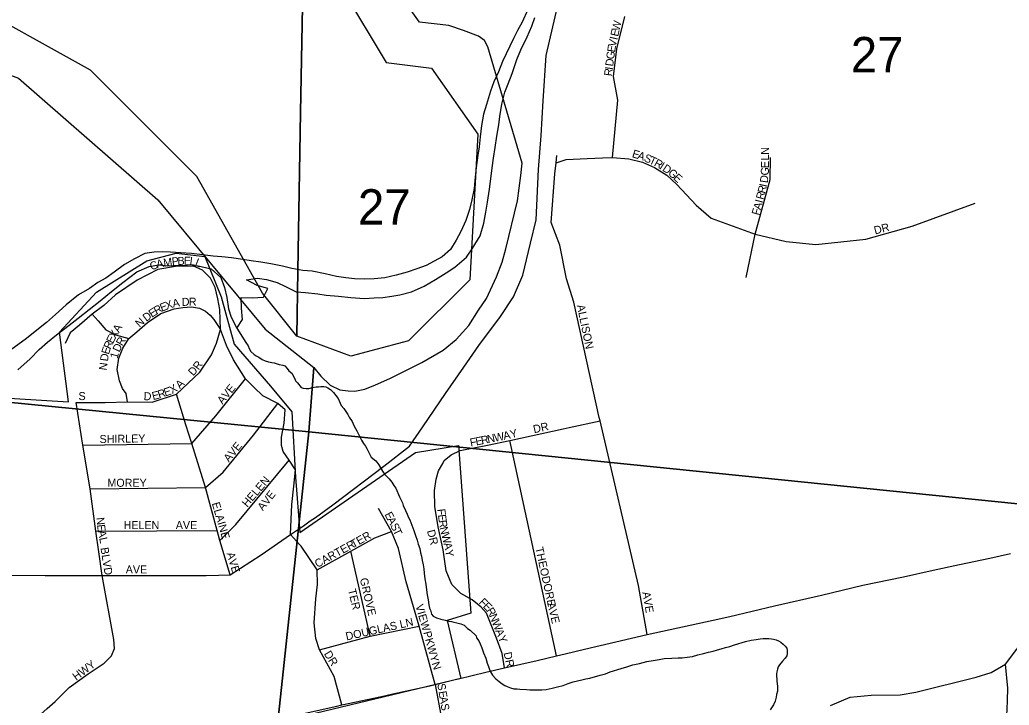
# Model space of a CAD drawing. Extents: x 1310247 to 1552180, y 377264 to 706493.
# Drawn here: x 1392274 to 1398452, y 517629 to 521908 of the extents above; entities that cross this region are included whole.
import ezdxf

# ---------------------------------------------------------------- set-up
doc = ezdxf.new("R2010")
doc.units = 0
for name, color, linetype in [('GM_X_City_Street', 7, 'Continuous'), ('GM_X_City_Street_Text', 7, 'Continuous'), ('GM_X_Corporation', 7, 'Continuous'), ('GM_X_County_Road', 7, 'Continuous'), ('GM_X_Minor_River', 7, 'Continuous'), ('GM_X_Section', 7, 'Continuous'), ('GM_X_Section_Text', 7, 'Continuous'), ('GM_X_State_Route', 7, 'Continuous'), ('GM_X_Township_Subdivision', 7, 'Continuous'), ('GM_X_Township_Subdivision_Text', 7, 'Continuous')]:
    doc.layers.add(name, color=color, linetype=linetype)

msp = doc.modelspace()

# ---------------------------------------------------------------- linework, layer by layer
at = {"layer": 'GM_X_City_Street'}
for points in [[(1394020.5, 518632.6), (1393963.9, 518693.4), (1393973.5, 518882.1), (1393985.9, 518995.3), (1393995.2, 519098), (1393956.7, 519158.4), (1393919.5, 519212.6), (1393907.3, 519250.2), (1393908.9, 519301), (1393924.7, 519390.4), (1393931, 519472.4), (1393884.7, 519511.3), (1393791.9, 519560.3), (1393737.3, 519611.9), (1393683.6, 519666.2), (1393609.5, 519785.1), (1393564.4, 519875.2), (1393527.1, 519974.9), (1393522.2, 520099), (1393511.4, 520164.8), (1393494.7, 520235.6), (1393464.2, 520294.5), (1393415.1, 520343.6), (1393359.1, 520369.2), (1393259.8, 520368.8), (1393137, 520349.5), (1393007.4, 520281.7), (1392871.8, 520191.3), (1392798.1, 520124.6), (1392726.3, 520069.5), (1392647.8, 520000.8), (1392587.8, 519952.6), (1392557.4, 519887.1)], [(1392726.3, 520069.5), (1392763.7, 520027.6), (1392811.5, 519973), (1392871.9, 519941.6), (1392954.8, 519918), (1393004.8, 519959.6), (1393072.1, 520017.3), (1393153.8, 520073.5), (1393238.7, 520103.3), (1393292.2, 520111.7), (1393345.6, 520115.5), (1393396.1, 520107.5), (1393432.8, 520088.8), (1393461.8, 520063.9), (1393485.9, 520036), (1393527.1, 519974.9)], [(1392626.2, 519518.4), (1392807.9, 519518.4), (1392946.4, 519522.3), (1393101, 519520.5), (1393252.1, 519570.1), (1393397.3, 519707.2), (1393472, 519816.5), (1393503.1, 519887.8), (1393527.1, 519974.9)], [(1392946.4, 519522.3), (1392939.1, 519574.5), (1392916.2, 519606.6), (1392896.3, 519653.2), (1392881.4, 519723.5), (1392891.7, 519795.7), (1392918.1, 519857.6), (1392954.8, 519918)], [(1392668.4, 519251.1), (1393348.6, 519261.9), (1393499.1, 519435.8), (1393683.6, 519666.2)], [(1393588.2, 518442.7), (1393523.7, 518657.5), (1393507.2, 518719.7), (1393432.8, 518986.8), (1393348.6, 519261.9), (1393311.6, 519379.1), (1393252.1, 519570.1)], [(1392788.3, 518437.6), (1392767.6, 518586), (1392749.9, 518714.7), (1392712.6, 518979), (1392668.4, 519251.1), (1392626.2, 519518.4)], [(1392712.6, 518979), (1393432.8, 518986.8), (1393544.5, 519084.2), (1393733.5, 519314.8), (1393884.7, 519511.3)], [(1393523.7, 518657.5), (1393622.5, 518757.4), (1393956.7, 519158.4)], [(1395131.4, 518259.9), (1395098.2, 518287.5), (1395028.6, 518327.1), (1394970.8, 518381.7), (1394936.5, 518467.3), (1394918.3, 518597.9), (1394886.2, 518741.4), (1394865.8, 518869.9), (1394862.6, 518968.4), (1394873.4, 519039.1), (1394889.4, 519091.5), (1394914.8, 519138.5)], [(1394868.3, 517759), (1394768.5, 518122.7), (1394687.4, 518397.9), (1394639.3, 518607), (1394595.1, 518713.9), (1394513.1, 518855.7)], [(1392749.9, 518714.7), (1393507.2, 518719.7)], [(1393963.9, 518693.4), (1394044.6, 518748.8)], [(1394044.6, 518748.8), (1394087.8, 518778.8)], [(1393515.3, 518440.8), (1393588.2, 518442.7), (1393780.4, 518567.7), (1393963.9, 518693.4)], [(1394131.5, 518474), (1394341.8, 518589.5), (1394492, 518674.3), (1394595.1, 518713.9)], [(1394284.8, 517630.6), (1394237.7, 517807.4), (1394146.5, 517975), (1394121.6, 518045.1), (1394111.7, 518142.3), (1394123.5, 518292.9), (1394133, 518382.8), (1394131.5, 518474), (1394030, 518622.4), (1394020.5, 518632.6)], [(1394462.5, 518059.8), (1394341.8, 518589.5)], [(1391836.9, 518432), (1392130, 518439.6), (1392431.6, 518437.6), (1392728.5, 518437.6)], [(1392494.4, 517652.3), (1392498.4, 517655.9), (1392583, 517739.8), (1392700.5, 517823.8), (1392801.2, 517890.2), (1392847.2, 517937.3), (1392866, 517983.2), (1392861.3, 518038.4), (1392788.3, 518437.6)], [(1392728.5, 518437.6), (1392788.3, 518437.6), (1393437.8, 518438.8), (1393515.3, 518440.8)], [(1394146.5, 517975), (1394462.5, 518059.8), (1394768.5, 518122.7)], [(1394868.3, 517759), (1394907.7, 517546.6), (1394907.6, 517283.5), (1394873.3, 517089.1), (1394873.3, 516871.8), (1394912.6, 516713.4)], [(1392068.2, 517328), (1392161, 517385), (1392345.9, 517519.6), (1392445.2, 517607.7), (1392494.4, 517652.3)]]:
    msp.add_lwpolyline(points, dxfattribs=at)
at = {"layer": 'GM_X_Corporation'}
msp.add_lwpolyline([(1391869.2, 519567.2), (1392578.1, 519522.3), (1392522.6, 519958.1), (1392752.4, 520206.4), (1393066.9, 520402.2), (1393250.9, 520450.5), (1393428.7, 520430.1), (1393531.7, 520178.3), (1393613.5, 519883), (1393838.6, 519619.8), (1393972.4, 519459.4), (1393994.7, 519051.4), (1394023.6, 518707.7), (1394745.3, 519206.8), (1395013.3, 519249.4), (1395089.9, 518204.1), (1394941.8, 518157.7), (1395027.6, 517796.1), (1393642.8, 517462.9)], dxfattribs=at)
at = {"layer": 'GM_X_County_Road'}
msp.add_lwpolyline([(1394087.8, 518778.8), (1394120.3, 518801.4), (1394228.7, 518879.2), (1394546.3, 519121.1), (1394708.3, 519246.3), (1394791.4, 519366.2), (1394931.3, 519574.5), (1395045.9, 519739.6), (1395140.6, 519875.3), (1395275.2, 520056.2), (1395356.2, 520178.2), (1395415.1, 520312.8), (1395463.5, 520513.7), (1395499.2, 520658.8), (1395513.9, 520973.3), (1395529.7, 521184.7), (1395541.3, 521401.4), (1395561.3, 521685.4), (1395638.1, 522015.6)], dxfattribs=at)
at = {"layer": 'GM_X_Minor_River'}
for points in [[(1395447.2, 521971.5), (1395410.7, 521892.5), (1395381.1, 521841.2), (1395357.5, 521789.9), (1395288.9, 521647.6), (1395262.9, 521582.3), (1395234.9, 521521), (1395213, 521461.6), (1395188.4, 521378.1), (1395170.5, 521318.5), (1395156.3, 521246.8), (1395148.1, 521176.9), (1395142.1, 521115), (1395134.5, 521063.1), (1395124, 520985.2), (1395115.5, 520905.3), (1395111.9, 520855.3), (1395097.7, 520783.5), (1395081.8, 520723.9), (1395059.6, 520654.4), (1395027.4, 520585.3), (1394999.7, 520532), (1394963.8, 520473), (1394912.4, 520428.5), (1394861.4, 520400), (1394810.5, 520373.5), (1394753.8, 520353.2), (1394693.1, 520331.1), (1394624.5, 520313.2), (1394553.9, 520297.3), (1394487.6, 520291.4), (1394423.5, 520287.4), (1394363.5, 520291.2), (1394309.6, 520296.9), (1394251.8, 520304.7), (1394180.3, 520321), (1394098.7, 520337.6), (1394040.8, 520343.4), (1393973.2, 520355.5), (1393913.5, 520369.4), (1393841.9, 520383.7), (1393778.2, 520393.7), (1393718.4, 520403.6), (1393666.6, 520411.2), (1393596.9, 520421.4), (1393535, 520427.3), (1393481.1, 520431), (1393415.3, 520441.1), (1393345.5, 520449.3), (1393277.6, 520453.4), (1393215.6, 520457.3), (1393165.6, 520458.9), (1393113.5, 520456.5), (1393055.2, 520448.3), (1392990.1, 520416.3), (1392926.9, 520380.1), (1392863.3, 520332), (1392812.1, 520295.5), (1392761.2, 520267), (1392710, 520230.5), (1392640.7, 520190.6), (1392562.7, 520128.9), (1392496.7, 520068.8), (1392441.1, 520018.4), (1392307.6, 519912.3), (1392223.6, 519850.8)], [(1392261.7, 519723.3), (1392337.9, 519791.1), (1392395.8, 519849.4), (1392447.3, 519895.9), (1392502.7, 519940.3), (1392582.7, 520002), (1392638.1, 520044.3), (1392707.9, 520098.3), (1392775.6, 520152.3), (1392847.6, 520212.2), (1392917.4, 520268.2), (1393005.5, 520333.6), (1393082.7, 520367.3), (1393143, 520377.4), (1393196.9, 520371.7), (1393269.1, 520375.5), (1393321.1, 520373.9), (1393387.1, 520371.8), (1393468.6, 520353.2), (1393529, 520299.2), (1393553, 520236.3), (1393567.1, 520173.7), (1393576.9, 520103.3), (1393593.2, 520050.6), (1393629.2, 519983.4), (1393664.9, 520036.4), (1393659, 520106.7), (1393657.2, 520174.9), (1393725.1, 520170.8), (1393795.4, 520176.6), (1393823.1, 520229.9), (1393755.6, 520248), (1393690.6, 520284.1), (1393759, 520294), (1393814.8, 520286.3), (1393880.3, 520268.2), (1393933.6, 520242.5), (1394000.6, 520208.3), (1394058.5, 520204.5), (1394134.3, 520196.1), (1394186.1, 520188.5), (1394264, 520182.1), (1394341.8, 520173.6), (1394425.7, 520167), (1394485.9, 520171.1), (1394540, 520173.5), (1394596.3, 520181.7), (1394646.6, 520190.2), (1394719.3, 520210), (1394798.5, 520245.6), (1394869.8, 520285.5), (1394937.2, 520327.5), (1394990.4, 520363.9), (1395062.4, 520425.8), (1395098.1, 520476.8), (1395148.7, 520559.4), (1395171.2, 520638.9), (1395183.3, 520706.7), (1395195.3, 520768.5), (1395207.9, 520850.3), (1395215.9, 520914.2), (1395224.1, 520984.1), (1395232, 521044), (1395242, 521109.8), (1395252.3, 521181.7), (1395264.5, 521251.5), (1395272.1, 521303.3), (1395284.6, 521381.1), (1395302.9, 521454.8), (1395322.6, 521508.3), (1395348.6, 521571.6), (1395377.4, 521658.9), (1395403.3, 521720.3), (1395441.9, 521801.2), (1395472, 521868.5), (1395489.7, 521922)], [(1393629.2, 519983.4), (1393685.7, 519892.6), (1393699.3, 519872.3), (1393706.9, 519856.1), (1393716.5, 519837.8), (1393738, 519817.3), (1393749.9, 519809), (1393765.7, 519800.6), (1393787.4, 519786), (1393805.3, 519779.5), (1393827.2, 519773), (1393847.1, 519768.5), (1393863.1, 519766.1), (1393892.9, 519755.3), (1393916.8, 519750.7), (1393928.7, 519746.4), (1393944.4, 519730), (1393954.1, 519715.8), (1393971.7, 519701.3), (1393991, 519666.8), (1393994.6, 519652.7), (1394008.4, 519640.4), (1394031.7, 519611.8), (1394043.7, 519607.5), (1394061.6, 519605), (1394079.7, 519606.5), (1394101.9, 519612), (1394124, 519615.4), (1394140.1, 519617), (1394154.2, 519618.7), (1394172.2, 519618.2), (1394184.1, 519615.9), (1394198, 519609.5), (1394213.8, 519599.1), (1394233.4, 519580.6), (1394247, 519562.3), (1394262.6, 519543.9), (1394281.6, 519499.4), (1394297.1, 519481), (1394322.3, 519444.4), (1394329.9, 519426.2), (1394349.3, 519399.7), (1394362.7, 519371.3), (1394378, 519340.9), (1394408.7, 519284.1), (1394420.2, 519261.9), (1394431.8, 519245.6), (1394441.5, 519231.3), (1394456.7, 519198.9), (1394468.2, 519176.6), (1394497.7, 519153.9), (1394515.2, 519129.4), (1394538.2, 519088.8), (1394553.8, 519068.4), (1394581.2, 519041.7), (1394596.8, 519021.3), (1394610.3, 519001), (1394621.9, 518982.7), (1394644.7, 518930.1), (1394663.8, 518891.6), (1394667.4, 518875.5), (1394682.7, 518845.1), (1394692.2, 518820.9), (1394701.7, 518800.6), (1394709.4, 518786.5), (1394715, 518770.3), (1394733.8, 518719.8), (1394745.1, 518687.5), (1394754.4, 518659.3), (1394761.8, 518633.1), (1394771.2, 518606.8), (1394776.6, 518580.7), (1394782, 518558.6), (1394787.4, 518532.4), (1394792.8, 518504.3), (1394796.2, 518480.2), (1394799.5, 518452.1), (1394802.7, 518418), (1394809.9, 518383.8), (1394813.1, 518349.8), (1394818.3, 518317.6), (1394823.6, 518287.5), (1394828.9, 518255.3), (1394832.4, 518235.2), (1394838.1, 518221.1), (1394845.5, 518196.9), (1394855.2, 518184.6), (1394877, 518174.1), (1394902.9, 518165.4), (1394930.8, 518158.7), (1394952.7, 518154.2), (1394970.7, 518151.7), (1394984.6, 518147.4)], [(1394984.6, 518147.4), (1395002.5, 518142.9), (1395028.4, 518136.2), (1395048.3, 518127.8), (1395069.8, 518107.2), (1395085.6, 518096.8), (1395122.8, 518061.8), (1395126.6, 518049.8), (1395140.2, 518031.4), (1395149.7, 518011.2), (1395159.1, 517986.9), (1395170.4, 517956.6), (1395183.6, 517922.3), (1395192.9, 517892), (1395200.4, 517869.8), (1395206, 517851.7), (1395213.7, 517837.5), (1395225.2, 517817.2), (1395246.6, 517792.7), (1395268.3, 517776.1), (1395286, 517761.7), (1395301.8, 517751.3), (1395317.7, 517744.9), (1395337.5, 517736.4), (1395359.4, 517731.8), (1395379.5, 517731.3), (1395397.4, 517728.8), (1395437.5, 517727.8), (1395459.5, 517725.3), (1395483.5, 517724.6), (1395507.5, 517724), (1395533.6, 517725.4), (1395561.7, 517726.7), (1395598, 517735.8), (1395632.3, 517742.9), (1395666.5, 517752), (1395698.9, 517765.2), (1395729.2, 517774.4), (1395757.4, 517781.7), (1395783.6, 517787), (1395807.8, 517792.4), (1395834, 517797.8), (1395898.6, 517816.1), (1395930.9, 517825.3), (1395961.2, 517836.5), (1396029.9, 517858.8), (1396064.2, 517867.9), (1396102.5, 517881), (1396142.8, 517889.9), (1396189.2, 517900.8), (1396229.5, 517907.7), (1396265.7, 517914.8), (1396297.9, 517920), (1396346, 517922.8), (1396384.1, 517923.8), (1396410.2, 517925.1), (1396440.4, 517928.4), (1396474.6, 517933.5), (1396506.9, 517942.7), (1396543.2, 517951.8), (1396575.4, 517959), (1396603.6, 517966.2), (1396629.9, 517973.6), (1396654.1, 517981), (1396680.3, 517988.3), (1396708.5, 517995.6), (1396736.8, 518004.9), (1396805.5, 518027.1), (1396841.7, 518034.2), (1396871.9, 518039.5), (1396896.1, 518042.8), (1396916.1, 518044.3), (1396938.2, 518045.8), (1396952.2, 518045.4), (1396968.2, 518043), (1396980.2, 518040.7), (1396996.1, 518036.3), (1397012, 518029.9), (1397025.8, 518021.5), (1397041.6, 518009.1), (1397053.3, 517996.8), (1397063, 517984.6), (1397066.7, 517970.5), (1397066.3, 517952.5), (1397063.9, 517936.6), (1397053.5, 517922.8), (1397037, 517903.2), (1397018.5, 517881.7), (1397010.1, 517867.9), (1397005.8, 517854), (1397001.4, 517838.1), (1396999, 517824.2), (1396998.7, 517808.2), (1397000.3, 517794.2), (1397001.9, 517778.1), (1397005.2, 517748), (1397004.5, 517716.1), (1397000, 517696.2), (1396997.5, 517678.2), (1396990.9, 517654.4), (1396980.4, 517630.7)], [(1396980.4, 517630.7), (1396959.6, 517599.2)]]:
    msp.add_lwpolyline(points, dxfattribs=at)
at = {"layer": 'GM_X_Section'}
for points in [[(1388864, 524337.7), (1393058, 524239.9), (1394049.8, 522831.1), (1394046.2, 522323.2), (1394027.5, 521329.5), (1394010.9, 520339.9), (1394003.6, 519932), (1393789.7, 520200.9), (1393380.3, 520928.3), (1392715.5, 521593.6), (1391874.1, 522060.8), (1390785, 522099.7), (1390127.5, 521772.7), (1389556.9, 521313.7), (1389203.2, 520889.8), (1388807.8, 520564.8)], [(1394049.8, 522831.1), (1394289, 522095.6), (1394562.6, 521641.4), (1394845.8, 521604.9), (1395134.4, 521194.3), (1395083.6, 520283.4), (1394700.9, 519904.1), (1394340.7, 519808.3), (1394003.6, 519932), (1394010.9, 520339.9), (1394027.5, 521329.5), (1394046.2, 522323.2)], [(1388967.2, 519839.1), (1389000.5, 520246.4), (1389415.2, 520712.9), (1390081.6, 521429.7), (1390739, 521750.7), (1391502.8, 521829.3), (1392266.3, 521543.8), (1393137, 520783.9), (1393806.6, 519976.5), (1394111.1, 519737.5), (1394077.9, 519336.3)], [(1394077.9, 519336.3), (1393469.6, 513633.9), (1388423.3, 514157.2), (1388967.2, 519839.1)], [(1399715, 518763.5), (1399128.9, 513068.6), (1393469.6, 513633.9), (1394077.9, 519336.3)]]:
    msp.add_lwpolyline(points, close=True, dxfattribs=at)
msp.add_lwpolyline([(1399715, 518763.5), (1394077.9, 519336.3), (1394111.1, 519737.5), (1394153.9, 519682.6), (1394212.6, 519627.2), (1394271.9, 519597.9), (1394323.8, 519590.7), (1394365.7, 519589.7), (1394428, 519602.3), (1394494.6, 519628.8), (1394585.5, 519668.7), (1394783.8, 519768.2), (1394917.6, 519845.1), (1394999.1, 519911.3), (1395077.1, 519999.5), (1395137.3, 520094.1), (1395189, 520167), (1395250.1, 520303.6), (1395286.2, 520394.8), (1395308.1, 520478.3), (1395380.9, 520776.6), (1395402.6, 520936.1), (1395410.3, 521011.9), (1395380.7, 521118.6), (1395196.9, 521738.9), (1395175.8, 521777.3), (1395138.4, 521806.2), (1395045.2, 521840.3), (1394954, 521872.4), (1394770.4, 521892.6), (1394580.5, 522159)], dxfattribs=at)
at = {"layer": 'GM_X_State_Route'}
for points in [[(1396707.3, 518183.3), (1396986.9, 518248.9), (1397280.2, 518316.4), (1397537.4, 518378.3), (1397793.1, 518429.9), (1397978, 518471.8), (1398140.9, 518506.6), (1398330.6, 518547.7), (1398459.9, 518575.3)], [(1395679, 517950.4), (1395799.8, 517979.5), (1396191.5, 518069.4), (1396603.2, 518158.9), (1396707.3, 518183.3)], [(1395013.2, 517793.8), (1395185.1, 517835.2), (1395300.4, 517861.5), (1395504.5, 517908.2), (1395625.5, 517937.4), (1395679, 517950.4)], [(1394603, 517699.2), (1394833.6, 517750.7), (1394868.3, 517759), (1395009.3, 517792.9), (1395013.2, 517793.8)], [(1393318.9, 517414.5), (1393391.4, 517429.3), (1393674.6, 517490.9), (1394000, 517565.8), (1394253.1, 517623.8), (1394284.8, 517630.6), (1394532.3, 517683.4), (1394594.6, 517697.3), (1394603, 517699.2)]]:
    msp.add_lwpolyline(points, dxfattribs=at)
at = {"layer": 'GM_X_Township_Subdivision'}
for points in [[(1395975.8, 521047.5), (1396007.5, 521406.3), (1395981.6, 521553.9), (1396001.6, 521725.4), (1396051.4, 521928.8)], [(1396191.5, 518069.4), (1396137.7, 518376.6), (1395897, 519404.8), (1395892.4, 519424.7), (1395733.4, 520144), (1395688.3, 520290), (1395645.6, 520501.1), (1395592.5, 520642.2), (1395614.5, 520946.5), (1395622.3, 521015.6), (1395627.4, 521060.5)], [(1395622.3, 521015.6), (1395686.4, 521035.2), (1395816.5, 521041.1), (1395912.3, 521045), (1395975.8, 521047.5), (1396078, 521040.1), (1396162.3, 521018.4), (1396238.3, 520985.8), (1396313.4, 520937.4), (1396376, 520878.9), (1396497.1, 520749.5), (1396590.2, 520670.2), (1396865.5, 520568.5), (1397059, 520524.2), (1397245.1, 520505), (1397557.3, 520538.4), (1397846.2, 520618.5), (1398239.4, 520762.2)], [(1396810.1, 520298.1), (1396865.5, 520568.5), (1396960.3, 520911.3), (1396961.9, 521048.5)], [(1395705, 519363.2), (1395897, 519404.8)], [(1394914.8, 519138.5), (1394924.7, 519156.8), (1394967.6, 519192.2), (1395024.5, 519218.6), (1395194.6, 519252.1), (1395333.7, 519282.1), (1395666.7, 519354.9), (1395705, 519363.2)], [(1395625.5, 517937.4), (1395341.3, 519243.1), (1395333.7, 519282.1)], [(1395300.4, 517861.5), (1395285.5, 517952.4), (1395250.2, 518046.6), (1395226.7, 518108.7), (1395189.2, 518204), (1395154.9, 518240.4), (1395131.4, 518259.9)], [(1397336, 517627), (1397459.4, 517678.8), (1397590.8, 517690.7), (1397772.1, 517692.7), (1397869.6, 517710.6), (1398245.1, 517803.7), (1398339.6, 517832.1), (1398429.6, 517885.5), (1398500.2, 517979.2), (1398568.1, 518101.5), (1398660.1, 518266.6)], [(1397962.8, 517457.2), (1398220.1, 517439.7), (1398327.6, 517433.7), (1398361.5, 517449.7), (1398399.3, 517479.6), (1398435.2, 517529.4), (1398440.4, 517603), (1398441.8, 517658.7), (1398444.5, 517736.1), (1398429.6, 517885.5)]]:
    msp.add_lwpolyline(points, dxfattribs=at)

# ---------------------------------------------------------------- texts
at = {"layer": 'GM_X_City_Street_Text'}
for s, rotation, p in [('C', 23.40269, (1393097.9, 520341.8)), ('A', 12.20162, (1393131.8, 520356.7)), ('M', 8.03995, (1393173.9, 520365.8)), ('P', 6.65397, (1393225.8, 520373.2)), ('B', 1.53011, (1393259.6, 520377.2)), ('E', 359.45356, (1393298.7, 520378.2)), ('L', 352.32773, (1393332.3, 520378)), ('L', 338.57905, (1393364.1, 520374.1)), ('E', 21.75067, (1393160.1, 520084.5)), ('X', 19.10541, (1393192.2, 520097.4)), ('A', 11.10634, (1393232, 520111.3)), ('D', 2.07701, (1393286.2, 520121.2)), ('R', 0.1457, (1393329.7, 520122.8)), ('D', 36.03058, (1393063.8, 520020.9)), ('E', 34.04624, (1393099, 520046.5)), ('R', 29.75994, (1393127.3, 520065.7)), ('N', 41.72973, (1393021.8, 519984.1)), ('X', 59.3455, (1392870.8, 519913.3)), ('A', 59.36356, (1392893.3, 519951.1)), ('R', 65.7811, (1392839.6, 519847)), ('E', 63.50825, (1392855.6, 519882.6)), ('R', 59.359, (1392913.9, 519867.7)), ('E', 72.76168, (1392829.7, 519814.8)), ('D', 64.69592, (1392895.7, 519829)), ('D', 82.1063, (1392824.1, 519773.3)), ('1', 75.51702, (1392884.1, 519789.2)), ('R', 53.19843, (1393390.4, 519717.3)), ('N', 82.11868, (1392816.3, 519716.7)), ('D', 46.39906, (1393356, 519680.5)), ('A', 44.34624, (1393274.5, 519600.9)), ('S', 0.00001, (1392640.8, 519533.5)), ('D', 357.81378, (1393046.8, 519533.4)), ('E', 13.97941, (1393106.1, 519533.3)), ('R', 18.22752, (1393144.1, 519542.9)), ('E', 18.29091, (1393181.8, 519555.4)), ('X', 29.5048, (1393225, 519570.7)), ('AVE', 50.70734, (1393539.9, 519503.6)), ('SHIRLEY', 0.97049, (1392772.6, 519265.1)), ('AVE', 50.4402, (1393579.5, 519142.9)), ('MOREY', 0.00001, (1392821.2, 518992.3)), ('HELEN', 49.39793, (1393694.1, 518861.4)), ('AVE', 51.95206, (1393792.3, 518838.8)), ('ELAINE', 286.26004, (1393472.6, 518888.7)), ('F', 276.94205, (1394880.9, 518852)), ('N', 276.11939, (1392751.4, 518799)), ('E', 297.50595, (1394549.9, 518820)), ('A', 297.51215, (1394566.2, 518788.8)), ('E', 276.94205, (1394885.2, 518817)), ('R', 278.20908, (1394889.6, 518780.9)), ('E', 276.94109, (1392756.1, 518754.5)), ('HELEN', 0.00001, (1392922.4, 518728.2)), ('AVE', 0.00001, (1393248, 518728.3)), ('S', 296.91937, (1394586.4, 518749.9)), ('T', 294.7074, (1394602.2, 518719)), ('DR', 284.74583, (1394816, 518717.2)), ('N', 283.16307, (1394896.1, 518737)), ('A', 280.82709, (1392760.9, 518715.9)), ('L', 281.88525, (1392769.4, 518671.7)), ('TER', 29.47087, (1394356.6, 518608.3)), ('W', 283.94493, (1394906.3, 518693.5)), ('BLVD', 278.97293, (1392777.7, 518610.3)), ('CARTER', 28.94789, (1394132.2, 518485.1)), ('A', 282.62601, (1394920, 518638.3)), ('Y', 278.84422, (1394929.5, 518596.2)), ('AVE', 286.50299, (1393565, 518576.3)), ('AVE', 0.00001, (1392935.6, 518451.1)), ('GROVE', 283.17416, (1394396.7, 518417.4)), ('TER', 283.49607, (1394322.8, 518349.2)), ('VIEW', 285.94582, (1394744.2, 518250.6)), ('DOUGLAS LN', 12.59918, (1394314.7, 518032.8)), ('PKWY', 285.37804, (1394792.6, 518083.4)), ('DR', 302.00785, (1394171.2, 517949.4)), ('HWY', 36.53175, (1392626.3, 517780.3)), ('N', 288.4386, (1394845.3, 517890.2)), ('S', 279.39945, (1394880.9, 517761.2)), ('E', 279.39945, (1394888.8, 517713.5)), ('A', 279.4074, (1394894.5, 517678.8)), ('S', 279.39945, (1394901.7, 517635.3))]:
    msp.add_text(s, height=50, rotation=rotation, dxfattribs=at).set_placement(p)
at = {"layer": 'GM_X_Section_Text'}
for p in [(1397463.2, 521579.2), (1394385.4, 520628.8)]:
    msp.add_text('27', height=221, rotation=0.00001, dxfattribs=at).set_placement(p)
at = {"layer": 'GM_X_Township_Subdivision_Text'}
for s, rotation, p in [('W', 77.27696, (1396017.6, 521834.3)), ('E', 77.28433, (1396009.9, 521800)), ('E', 80.65447, (1395990.1, 521701.6)), ('V', 77.73429, (1395995.7, 521735.6)), ('I', 77.26739, (1396005, 521778.5)), ('G', 82.64726, (1395984.6, 521658.4)), ('D', 82.66077, (1395978.9, 521614.8)), ('R', 82.6581, (1395971.1, 521553.6)), ('I', 82.63642, (1395976.1, 521592.9)), ('E', 342.51558, (1396093.2, 521051)), ('A', 341.21949, (1396126.4, 521040.6)), ('S', 337.13322, (1396167.2, 521026.7)), ('N', 90, (1396952.2, 521064.8)), ('T', 335.54926, (1396199.3, 521013.2)), ('R', 330.77321, (1396230.4, 520999.1)), ('I', 327.41316, (1396264.3, 520980.2)), ('D', 325.65526, (1396282.5, 520968.6)), ('L', 90, (1396952.2, 521029.6)), ('E', 90, (1396952.2, 520981.2)), ('G', 319.05975, (1396317.6, 520944.7)), ('E', 317.6675, (1396350.6, 520916)), ('G', 87.48851, (1396950.2, 520934.9)), ('I', 77.44254, (1396938.4, 520860.3)), ('D', 82.46553, (1396944, 520886.5)), ('R', 74.93105, (1396917.2, 520781.5)), ('R', 74.93105, (1396927.5, 520819.8)), ('A', 74.93105, (1396900.1, 520717.8)), ('I', 74.93105, (1396911.5, 520760.3)), ('F', 74.93105, (1396890.9, 520683.8)), ('DR', 14.73648, (1397614.8, 520567.2)), ('ALLISON', 281.69062, (1395752, 520124.4)), ('A', 12.31797, (1395297.8, 519284.6)), ('Y', 14.6778, (1395343, 519294.5)), ('DR', 12.53266, (1395485.5, 519326.4)), ('F', 11.32868, (1395089.8, 519242.9)), ('E', 11.32404, (1395124.3, 519249.8)), ('R', 11.3357, (1395158.8, 519256.7)), ('N', 11.32922, (1395197.6, 519264.5)), ('W', 11.33354, (1395240.8, 519273.2)), ('THEODORE', 282.36276, (1395492.4, 518610.9)), ('F', 314.57503, (1395137.8, 518268)), ('AVE', 279.78103, (1396161.3, 518333.3)), ('E', 313.98577, (1395162.4, 518243)), ('R', 300.93461, (1395185, 518220.1)), ('AVE', 283.57069, (1395567.1, 518263.5)), ('N', 292.08351, (1395204.4, 518187.9)), ('W', 291.61095, (1395220.9, 518147.3)), ('A', 291.60252, (1395242, 518094.1)), ('Y', 291.60881, (1395258.2, 518053.2)), ('DR', 282.52946, (1395294.4, 517955.3))]:
    msp.add_text(s, height=50, rotation=rotation, dxfattribs=at).set_placement(p)

doc.saveas('drawing.dxf')
